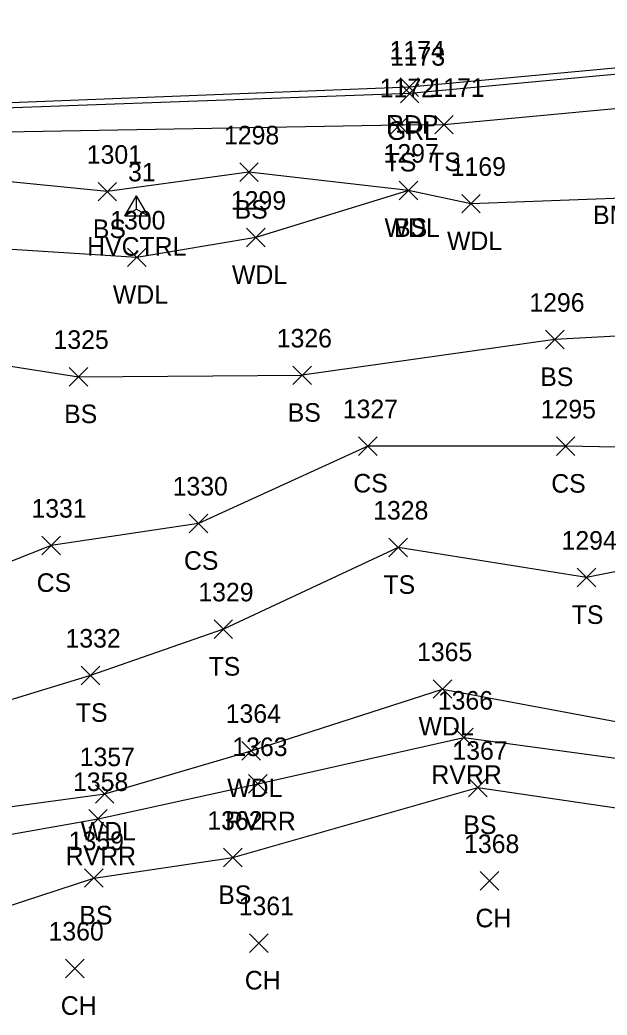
# Model space of a CAD drawing. Extents: x 1502119 to 1504100, y 606168 to 606406.
# Drawn here: x 1503672.8 to 1503736.1, y 606176.5 to 606283.7 of the extents above; entities that cross this region are included whole.
import ezdxf

# ---------------------------------------------------------------- set-up
doc = ezdxf.new("R2010")
doc.units = 0
for name, color, linetype in [('C_A', 7, 'Continuous'), ('C_C', 7, 'Continuous'), ('C_I', 7, 'Continuous'), ('CPSM', 7, 'Continuous'), ('L_A', 7, 'Continuous'), ('L_I', 7, 'Continuous'), ('L_TIC', 7, 'Continuous'), ('LAWA', 7, 'Continuous'), ('LAWE', 7, 'Continuous'), ('LELB', 7, 'Continuous'), ('P_A', 7, 'Continuous'), ('P_I', 7, 'Continuous'), ('P_TIC', 7, 'Continuous'), ('PET', 7, 'Continuous'), ('R_A', 7, 'Continuous'), ('R_I', 7, 'Continuous'), ('R_TIC', 7, 'Continuous'), ('RGR', 7, 'Continuous')]:
    doc.layers.add(name, color=color, linetype=linetype)

msp = doc.modelspace()

# ---------------------------------------------------------------- linework, layer by layer
at = {"layer": 'CPSM'}
for p, q in [((1503684.09, 606262.57), (1503685.34, 606264.74)), ((1503686.59, 606262.57), (1503685.34, 606264.74)), ((1503685.34, 606263.29), (1503685.34, 606264.74)), ((1503684.09, 606262.57), (1503685.34, 606263.29)), ((1503685.34, 606263.29), (1503685.34, 606263.29)), ((1503685.34, 606263.29), (1503686.59, 606262.57)), ((1503684.09, 606262.57), (1503686.59, 606262.57))]:
    msp.add_line(p, q, dxfattribs=at)
at = {"layer": 'L_TIC'}
for points in [[(1503712.68, 606271.36), (1503714.68, 606273.36)], [(1503714.68, 606271.36), (1503712.68, 606273.36)], [(1503717.48, 606271.4), (1503719.48, 606273.4)], [(1503719.48, 606271.4), (1503717.48, 606273.4)], [(1503696.47, 606266.28), (1503698.47, 606268.28)], [(1503698.47, 606266.28), (1503696.47, 606268.28)], [(1503681.2, 606264.19), (1503683.2, 606266.19)], [(1503683.2, 606264.19), (1503681.2, 606266.19)], [(1503713.66, 606264.31), (1503715.66, 606266.31)], [(1503715.66, 606264.31), (1503713.66, 606266.31)], [(1503713.66, 606264.31), (1503715.66, 606266.31)], [(1503715.66, 606264.31), (1503713.66, 606266.31)], [(1503720.39, 606262.89), (1503722.39, 606264.89)], [(1503722.39, 606262.89), (1503720.39, 606264.89)], [(1503697.22, 606259.24), (1503699.22, 606261.24)], [(1503699.22, 606259.24), (1503697.22, 606261.24)], [(1503684.38, 606257.11), (1503686.38, 606259.11)], [(1503686.38, 606257.11), (1503684.38, 606259.11)], [(1503729.42, 606248.25), (1503731.42, 606250.25)], [(1503731.42, 606248.25), (1503729.42, 606250.25)], [(1503678.1, 606244.25), (1503680.1, 606246.25)], [(1503680.1, 606244.25), (1503678.1, 606246.25)], [(1503702.2, 606244.4), (1503704.2, 606246.4)], [(1503704.2, 606244.4), (1503702.2, 606246.4)], [(1503702.2, 606244.4), (1503704.2, 606246.4)], [(1503704.2, 606244.4), (1503702.2, 606246.4)], [(1503709.27, 606236.78), (1503711.27, 606238.78)], [(1503711.27, 606236.78), (1503709.27, 606238.78)], [(1503730.6, 606236.76), (1503732.6, 606238.76)], [(1503732.6, 606236.76), (1503730.6, 606238.76)], [(1503691.02, 606228.45), (1503693.02, 606230.45)], [(1503693.02, 606228.45), (1503691.02, 606230.45)], [(1503675.15, 606226.07), (1503677.15, 606228.07)], [(1503677.15, 606226.07), (1503675.15, 606228.07)], [(1503712.55, 606225.86), (1503714.55, 606227.86)], [(1503714.55, 606225.86), (1503712.55, 606227.86)], [(1503732.84, 606222.62), (1503734.84, 606224.62)], [(1503734.84, 606222.62), (1503732.84, 606224.62)], [(1503693.71, 606217.05), (1503695.71, 606219.05)], [(1503695.71, 606217.05), (1503693.71, 606219.05)], [(1503679.4, 606212.07), (1503681.4, 606214.07)], [(1503681.4, 606212.07), (1503679.4, 606214.07)], [(1503717.32, 606210.61), (1503719.32, 606212.61)], [(1503719.32, 606210.61), (1503717.32, 606212.61)], [(1503719.62, 606205.39), (1503721.62, 606207.39)], [(1503721.62, 606205.39), (1503719.62, 606207.39)], [(1503696.7, 606203.96), (1503698.7, 606205.96)], [(1503698.7, 606203.96), (1503696.7, 606205.96)], [(1503697.42, 606200.39), (1503699.42, 606202.39)], [(1503699.42, 606200.39), (1503697.42, 606202.39)], [(1503721.13, 606199.99), (1503723.13, 606201.99)], [(1503723.13, 606199.99), (1503721.13, 606201.99)], [(1503680.92, 606199.3), (1503682.92, 606201.3)], [(1503682.92, 606199.3), (1503680.92, 606201.3)], [(1503680.2, 606196.62), (1503682.2, 606198.62)], [(1503682.2, 606196.62), (1503680.2, 606198.62)], [(1503694.72, 606192.45), (1503696.72, 606194.45)], [(1503696.72, 606192.45), (1503694.72, 606194.45)], [(1503679.75, 606190.25), (1503681.75, 606192.25)], [(1503681.75, 606190.25), (1503679.75, 606192.25)], [(1503722.39, 606189.94), (1503724.39, 606191.94)], [(1503724.39, 606189.94), (1503722.39, 606191.94)], [(1503697.53, 606183.24), (1503699.53, 606185.24)], [(1503699.53, 606183.24), (1503697.53, 606185.24)], [(1503677.7, 606180.51), (1503679.7, 606182.51)], [(1503679.7, 606180.51), (1503677.7, 606182.51)]]:
    msp.add_lwpolyline(points, dxfattribs=at)
at = {"layer": 'LAWA'}
for points in [[(1503949.06, 606292.95), (1503922.72, 606291.41), (1503895.88, 606293.14), (1503871.23, 606284.55), (1503848.49, 606280.84), (1503822.63, 606273.75), (1503793.16, 606269.59), (1503770.58, 606267.1), (1503744.52, 606264.72), (1503721.39, 606263.89), (1503714.66, 606265.31), (1503698.22, 606260.24), (1503685.38, 606258.11), (1503660.65, 606259.69), (1503652.68, 606259.1), (1503650.68, 606259.07), (1503643.68, 606257.82), (1503632.11, 606261.1), (1503598.78, 606263.09)], [(1503644.38, 606200.66), (1503661.82, 606197.6), (1503681.92, 606200.3), (1503697.7, 606204.96), (1503718.32, 606211.61), (1503749.72, 606205.75), (1503773.98, 606210.33), (1503804.12, 606207.66), (1503814.72, 606212.71), (1503825.12, 606213.47), (1503835.31, 606218.59), (1503851.96, 606217.91), (1503869.14, 606226.79), (1503894.25, 606229.09), (1503902.71, 606239.52), (1503913.47, 606247.57)]]:
    msp.add_lwpolyline(points, dxfattribs=at)
at = {"layer": 'LAWE'}
msp.add_lwpolyline([(1503614.85, 606213.1), (1503625.62, 606202.51), (1503635.42, 606197.97), (1503642.95, 606193.31), (1503660.89, 606194.04), (1503681.2, 606197.62), (1503698.42, 606201.39), (1503720.62, 606206.39), (1503749.7, 606202.44), (1503775.92, 606206.14), (1503802.08, 606202.28), (1503818.9, 606205.49), (1503835.44, 606207.89), (1503847.03, 606211.3), (1503876.78, 606218.57), (1503896.13, 606221.77), (1503905.66, 606233.48), (1503922.02, 606244.01), (1503934.31, 606243.71)], dxfattribs=at)
at = {"layer": 'LELB'}
for points in [[(1504084.2, 606316.18), (1504049.45, 606313.99), (1504016.18, 606312.8), (1504000.76, 606312.78), (1503990.22, 606311.65), (1503980.1, 606310.35), (1503956.75, 606307.04), (1503915.14, 606300.95), (1503869.77, 606289.77), (1503847.82, 606285.43), (1503820.78, 606281.87), (1503792.45, 606279.04), (1503767.54, 606276.84), (1503743.42, 606274.71), (1503718.48, 606272.4), (1503713.68, 606272.36), (1503654.98, 606271.32), (1503649.47, 606271.35), (1503622.06, 606272.76), (1503601.12, 606274.82)], [(1503984.83, 606255.06), (1503973.29, 606256.69), (1503955.93, 606260.62), (1503952.28, 606267.45), (1503924.4, 606275.03), (1503909.61, 606278), (1503896.78, 606282.99), (1503877.54, 606272.17), (1503862.1, 606272.45), (1503836.9, 606266.22), (1503825.65, 606259.98), (1503818.28, 606261.16), (1503806.2, 606257.22), (1503801.33, 606241.79), (1503784.67, 606238.5), (1503757.1, 606237.25), (1503731.6, 606237.76), (1503710.27, 606237.78), (1503692.02, 606229.45), (1503676.15, 606227.07), (1503663.08, 606221.89), (1503653.08, 606223.12)], [(1503714.66, 606265.31), (1503697.47, 606267.28), (1503682.2, 606265.19), (1503656.94, 606267.72), (1503649.68, 606268.24)], [(1503930, 606245.46), (1503918.92, 606249.17), (1503904.84, 606258.51), (1503879.8, 606256.17), (1503860.62, 606251.71), (1503849.74, 606241), (1503840.87, 606237.08), (1503831.29, 606226.33), (1503824.17, 606224.52), (1503818.07, 606222.32), (1503808.71, 606221.45), (1503786.64, 606226.93), (1503757.01, 606228.26), (1503733.84, 606223.62), (1503713.55, 606226.86), (1503694.71, 606218.05), (1503680.4, 606213.07), (1503668.25, 606209.35), (1503648.97, 606211.13)], [(1503818.07, 606222.32), (1503814.66, 606236.26), (1503815.99, 606248.23), (1503806.2, 606257.22), (1503785.15, 606254.84), (1503756.29, 606250.66), (1503730.42, 606249.25), (1503703.2, 606245.4)], [(1503661.94, 606247.92), (1503679.1, 606245.25), (1503703.2, 606245.4)], [(1503613.71, 606211.71), (1503624.23, 606201.38), (1503628.7, 606194.41), (1503640.82, 606186.16), (1503659.4, 606184.25), (1503680.75, 606191.25), (1503695.72, 606193.45), (1503722.13, 606200.99), (1503749.25, 606197.03), (1503775.84, 606202.19), (1503801.63, 606198.61), (1503818.14, 606200.65), (1503835.99, 606205), (1503847.21, 606209.11), (1503877.12, 606216.19), (1503896.03, 606218.36), (1503907.7, 606226.44), (1503929.55, 606235.83)]]:
    msp.add_lwpolyline(points, dxfattribs=at)
at = {"layer": 'P_TIC'}
for points in [[(1503713.75, 606275.43), (1503715.75, 606277.43)], [(1503715.75, 606275.43), (1503713.75, 606277.43)]]:
    msp.add_lwpolyline(points, dxfattribs=at)
at = {"layer": 'PET'}
msp.add_lwpolyline([(1504084.52, 606320.63), (1504050.65, 606320.45), (1504000.43, 606315.8), (1503956.16, 606310.12), (1503915.05, 606304.21), (1503867.85, 606296.91), (1503814.4, 606288.86), (1503766.38, 606281.21), (1503714.75, 606276.43), (1503655.34, 606274.1), (1503622.19, 606275.72), (1503601.58, 606277.52)], dxfattribs=at)
at = {"layer": 'R_TIC'}
for points in [[(1503713.79, 606274.76), (1503715.79, 606276.76)], [(1503715.79, 606274.76), (1503713.79, 606276.76)]]:
    msp.add_lwpolyline(points, dxfattribs=at)
at = {"layer": 'RGR'}
msp.add_lwpolyline([(1504084.44, 606319.87), (1504050.55, 606319.53), (1504000.64, 606315), (1503956.05, 606309.11), (1503915.05, 606302.99), (1503867.97, 606295.96), (1503814.82, 606287.72), (1503766.2, 606280.53), (1503714.79, 606275.76), (1503655.19, 606273.62), (1503622.1, 606275.05), (1503601.6, 606277)], dxfattribs=at)

# ---------------------------------------------------------------- texts
at = {"layer": 'C_A'}
msp.add_text('HVCTRL', height=2, dxfattribs=at).set_placement((1503680.03, 606258.29))
at = {"layer": 'C_C'}
msp.add_text('BM14=RRSIR IN M.POP ELEV:', height=2, dxfattribs=at).set_placement((1503734.55, 606261.69))
at = {"layer": 'C_I'}
msp.add_text('31', height=2, dxfattribs=at).set_placement((1503684.44, 606266.29))
at = {"layer": 'L_A'}
for s, p in [('TS', (1503712.09, 606267.36)), ('TS', (1503716.89, 606267.4)), ('BS', (1503695.92, 606262.28)), ('BS', (1503680.64, 606260.19)), ('WDL', (1503712.08, 606260.31)), ('BS', (1503713.1, 606260.31)), ('WDL', (1503718.81, 606258.89)), ('WDL', (1503695.64, 606255.24)), ('WDL', (1503682.8, 606253.11)), ('BS', (1503728.86, 606244.25)), ('BS', (1503677.55, 606240.25)), ('BS', (1503701.64, 606240.4)), ('BS', (1503701.64, 606240.4)), ('CS', (1503708.71, 606232.78)), ('CS', (1503730.04, 606232.76)), ('CS', (1503690.46, 606224.45)), ('CS', (1503674.59, 606222.07)), ('TS', (1503711.96, 606221.86)), ('TS', (1503732.25, 606218.62)), ('TS', (1503693.12, 606213.05)), ('TS', (1503678.81, 606208.07)), ('WDL', (1503715.74, 606206.61)), ('RVRR', (1503717.13, 606201.39)), ('WDL', (1503695.12, 606199.96)), ('RVRR', (1503694.93, 606196.39)), ('BS', (1503720.57, 606195.99)), ('WDL', (1503679.34, 606195.3)), ('RVRR', (1503677.72, 606192.62)), ('BS', (1503694.16, 606188.45)), ('BS', (1503679.19, 606186.25)), ('CH', (1503721.88, 606185.94)), ('CH', (1503697.02, 606179.24)), ('CH', (1503677.19, 606176.51))]:
    msp.add_text(s, height=2, dxfattribs=at).set_placement(p)
at = {"layer": 'L_I'}
for s, p in [('1172', (1503711.56, 606275.36)), ('1171', (1503716.92, 606275.4)), ('1298', (1503694.78, 606270.28)), ('1301', (1503679.99, 606268.19)), ('1297', (1503711.97, 606268.31)), ('1297', (1503711.97, 606268.31)), ('1169', (1503719.21, 606266.89)), ('1299', (1503695.52, 606263.24)), ('1300', (1503682.52, 606261.11)), ('1296', (1503727.68, 606252.25)), ('1325', (1503676.41, 606248.25)), ('1326', (1503700.46, 606248.4)), ('1326', (1503700.46, 606248.4)), ('1327', (1503707.58, 606240.78)), ('1295', (1503728.91, 606240.76)), ('1330', (1503689.24, 606232.45)), ('1331', (1503674.03, 606230.07)), ('1328', (1503710.85, 606229.86)), ('1294', (1503731.15, 606226.62)), ('1329', (1503692.01, 606221.05)), ('1332', (1503677.7, 606216.07)), ('1365', (1503715.58, 606214.61)), ('1366', (1503717.82, 606209.39)), ('1364', (1503694.96, 606207.96)), ('1363', (1503695.68, 606204.39)), ('1357', (1503679.23, 606203.3)), ('1367', (1503719.39, 606203.99)), ('1358', (1503678.51, 606200.62)), ('1362', (1503692.98, 606196.45)), ('1359', (1503678.05, 606194.25)), ('1368', (1503720.65, 606193.94)), ('1361', (1503696.36, 606187.24)), ('1360', (1503675.87, 606184.51))]:
    msp.add_text(s, height=2, dxfattribs=at).set_placement(p)
at = {"layer": 'P_A'}
msp.add_text('RDP', height=2, dxfattribs=at).set_placement((1503712.24, 606271.43))
at = {"layer": 'P_I'}
msp.add_text('1174', height=2, dxfattribs=at).set_placement((1503712.62, 606279.43))
at = {"layer": 'R_A'}
msp.add_text('GRL', height=2, dxfattribs=at).set_placement((1503712.33, 606270.76))
at = {"layer": 'R_I'}
msp.add_text('1173', height=2, dxfattribs=at).set_placement((1503712.66, 606278.76))

doc.saveas('drawing.dxf')
